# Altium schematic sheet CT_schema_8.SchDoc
size 274 x 160 mm
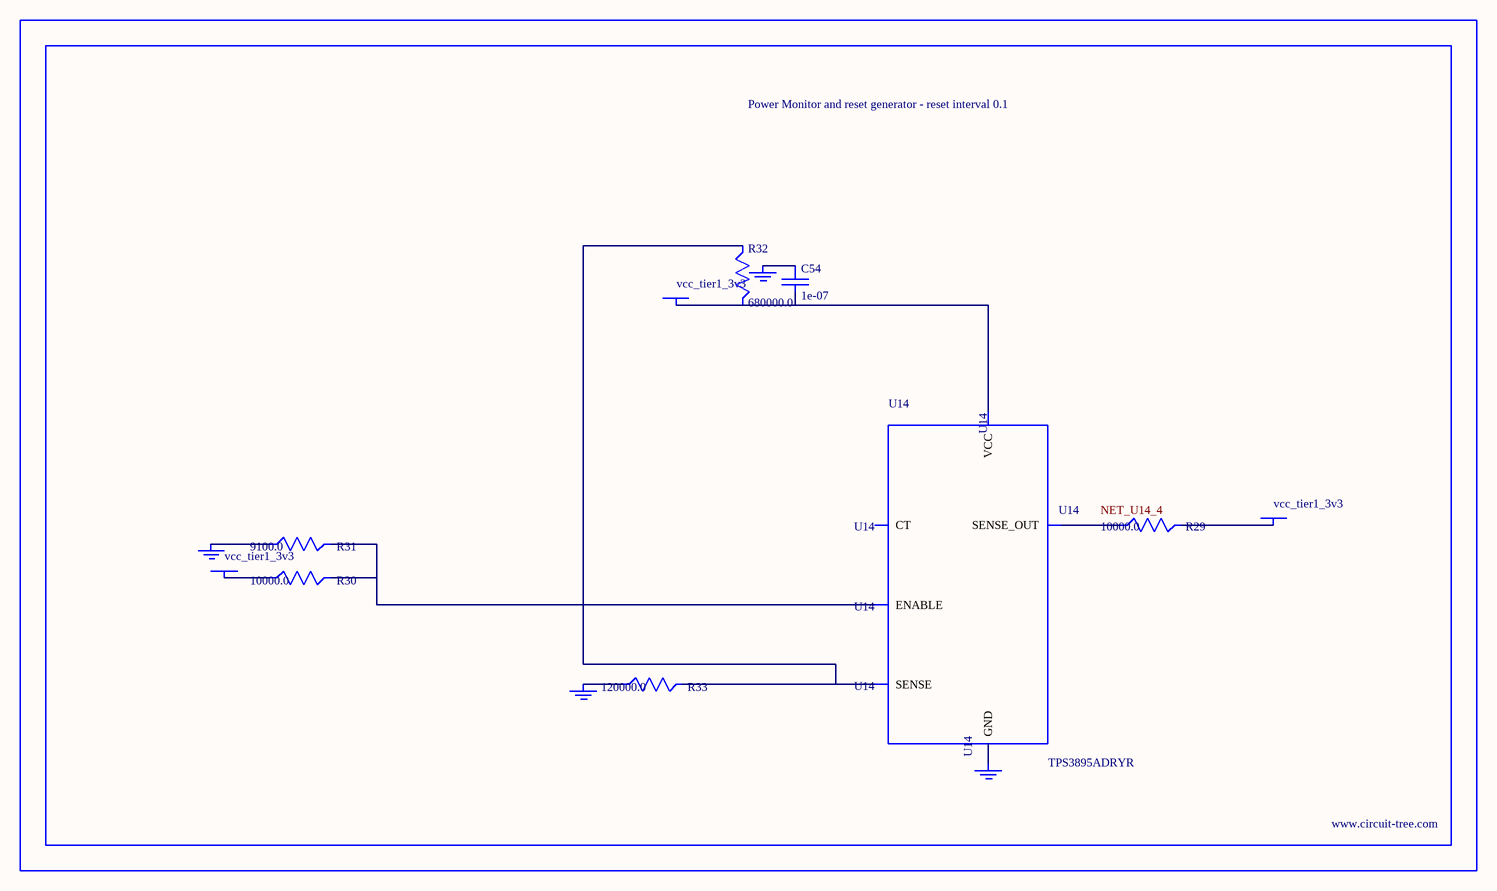
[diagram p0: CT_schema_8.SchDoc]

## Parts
BORDER7  (no value)
C54  1e-07  [C0402]
GND_INSTANCE_7_0  (no value)
GND_INSTANCE_7_1  (no value)
GND_INSTANCE_7_2  (no value)
GND_INSTANCE_7_3  (no value)
POWER_INSTANCE_7_0  vcc_tier1_3v3
POWER_INSTANCE_7_1  vcc_tier1_3v3
POWER_INSTANCE_7_2  vcc_tier1_3v3
R29  10000.0  [R0603]
R30  10000.0  [R0603]
R31  9100.0  [R0603]
R32  680000.0  [R0603]
R33  120000.0  [R0603]
U14  TPS3895ADRYR  [SON-6]

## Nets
NetC54_1: C54.1 GND_INSTANCE_7_2.0(GND)
NetC54_2: C54.2 POWER_INSTANCE_7_2.0(PWR) R32.2 U14.6(VCC)
NetGND_INSTANCE_7_0_0: GND_INSTANCE_7_0.0(GND) R31.1
NetGND_INSTANCE_7_1_0: GND_INSTANCE_7_1.0(GND) R33.1
NetGND_INSTANCE_7_3_0: GND_INSTANCE_7_3.0(GND) U14.2(GND)
NetPOWER_INSTANCE_7_0_0: POWER_INSTANCE_7_0.0(PWR) R30.1
NetPOWER_INSTANCE_7_1_0: POWER_INSTANCE_7_1.0(PWR) R29.2
NetR29_1: R29.1 U14.4(SENSE_OUT)
NetR30_2: R30.2 R31.2 U14.1(ENABLE)
NetR32_1: R32.1 R33.2 U14.3(SENSE)

Not connected (* = marked no-connect by the designer): U14 5(CT)

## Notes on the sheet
- Labels drawn without touching a wire or pin: NET_U14_4

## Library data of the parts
BORDER7 = BORDER_PAGE7
C54 = C0402C104K3RACTU
GND_INSTANCE_7_0-GND_INSTANCE_7_3 = GND
POWER_INSTANCE_7_0-POWER_INSTANCE_7_2 = PWR
R29 R30 = RC0603JR-0710KL
R31 = RC0603JR-079K1L
R32 = RC0603JR-07680KL
R33 = RC0603JR-07120KL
